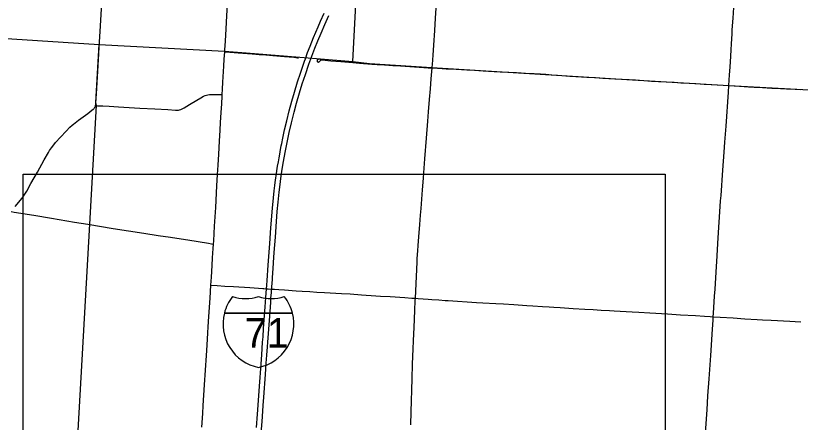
# Model space of a CAD drawing. Extents: x 1813937 to 1948437, y 826606 to 1022856.
# Drawn here: x 1873573 to 1890191, y 875827 to 884433 of the extents above; entities that cross this region are included whole.
import ezdxf

# ---------------------------------------------------------------- set-up
doc = ezdxf.new("R2010")
doc.units = 0
for name, color, linetype in [('Default', 7, 'Continuous'), ('GM_X_County_Road', 7, 'Continuous'), ('GM_X_Interstate_Route', 7, 'Continuous'), ('GM_X_Interstate_Shield', 7, 'Continuous'), ('GM_X_State_Route', 7, 'Continuous'), ('GM_X_Township', 7, 'Continuous'), ('GM_X_Township_Road', 7, 'Continuous')]:
    doc.layers.add(name, color=color, linetype=linetype)

msp = doc.modelspace()

# ---------------------------------------------------------------- linework, layer by layer
at = {"layer": 'Default'}
for p, q in [((1873729, 881082), (1887329, 881082)), ((1873729, 867482), (1873729, 881082)), ((1887329, 881082), (1887329, 867482))]:
    msp.add_line(p, q, dxfattribs=at)
at = {"layer": 'GM_X_County_Road'}
for points in [[(1875340, 883767), (1875347, 883875), (1875368, 884219), (1875408, 884824), (1875439, 885315), (1875466, 885691), (1875483, 885919), (1875493, 886066), (1875504, 886222), (1875516, 886361), (1875526, 886521)], [(1882394, 883327), (1882396, 883347), (1882399, 883397), (1882414, 883594), (1882429, 883806), (1882450, 884118), (1882466, 884380), (1882480, 884592), (1882489, 884773), (1882494, 884904), (1882502, 885051), (1882505, 885117), (1882513, 885297), (1882517, 885379), (1882523, 885510), (1882528, 885641), (1882535, 885805), (1882538, 885887), (1882542, 885985), (1882549, 886108)], [(1888677, 882955), (1888685, 883069), (1888692, 883183), (1888703, 883347), (1888718, 883576), (1888726, 883707), (1888734, 883838), (1888745, 884050), (1888750, 884132), (1888766, 884378), (1888781, 884607), (1888793, 884803), (1888810, 885032), (1888820, 885196), (1888836, 885408), (1888848, 885605), (1888852, 885654)], [(1875266, 882530), (1875266, 882534), (1875270, 882552), (1875273, 882582), (1875284, 882778), (1875304, 883138), (1875332, 883629), (1875340, 883767)], [(1882038, 878451), (1882059, 878916), (1882067, 879063), (1882075, 879227), (1882079, 879292), (1882092, 879456), (1882100, 879570), (1882113, 879750), (1882133, 880012), (1882147, 880208), (1882159, 880355), (1882177, 880550), (1882193, 880747), (1882211, 880992), (1882219, 881106), (1882242, 881401), (1882275, 881842), (1882302, 882202), (1882319, 882398), (1882339, 882659), (1882357, 882888), (1882375, 883100), (1882394, 883327)], [(1888348, 878062), (1888353, 878138), (1888376, 878498), (1888385, 878646), (1888407, 879006), (1888429, 879349), (1888446, 879611), (1888466, 879955), (1888479, 880167), (1888504, 880511), (1888512, 880625), (1888551, 881165), (1888578, 881541), (1888593, 881754), (1888619, 882097), (1888670, 882817), (1888677, 882955)], [(1873563, 880397), (1873708, 880574), (1873766, 880653), (1873810, 880722), (1873897, 880880), (1874034, 881123), (1874179, 881380), (1874268, 881537), (1874293, 881579), (1874329, 881637), (1874358, 881675), (1874420, 881751), (1874520, 881860), (1874642, 881992), (1874723, 882074), (1874772, 882118), (1874795, 882136), (1874902, 882219), (1875099, 882366), (1875189, 882435), (1875213, 882453), (1875226, 882465), (1875239, 882478), (1875244, 882483), (1875248, 882489), (1875253, 882497), (1875256, 882503), (1875261, 882512), (1875264, 882521), (1875266, 882530)], [(1881944, 875773), (1881952, 876049), (1881957, 876279), (1881964, 876508), (1881971, 876754), (1881981, 877049), (1881987, 877229), (1881993, 877376), (1881999, 877557), (1882012, 877835), (1882028, 878195), (1882036, 878408), (1882038, 878451)], [(1888128, 874784), (1888154, 875161), (1888190, 875701), (1888216, 876094), (1888235, 876388), (1888258, 876748), (1888294, 877238), (1888331, 877795), (1888344, 877991), (1888348, 878062)]]:
    msp.add_lwpolyline(points, dxfattribs=at)
at = {"layer": 'GM_X_Interstate_Route'}
for points in [[(1878674, 875720), (1878695, 875998), (1878743, 876686), (1878764, 876964), (1878785, 877258), (1878803, 877520), (1878812, 877635), (1878825, 877815), (1878858, 878273), (1878872, 878469), (1878886, 878654), (1878892, 878731), (1878899, 878829), (1878923, 879156), (1878956, 879615), (1878979, 879942), (1878997, 880187), (1879012, 880367), (1879024, 880498), (1879032, 880579), (1879048, 880726), (1879062, 880840), (1879071, 880905), (1879084, 881002), (1879096, 881083), (1879106, 881148), (1879121, 881246), (1879137, 881343), (1879151, 881423), (1879165, 881504), (1879183, 881601), (1879198, 881682), (1879207, 881730), (1879230, 881842), (1879268, 882019), (1879313, 882210), (1879365, 882417), (1879421, 882623), (1879476, 882812), (1879543, 883031), (1879604, 883218), (1879688, 883467), (1879708, 883521), (1879755, 883652), (1879808, 883790), (1879882, 883972), (1879977, 884199), (1880029, 884319), (1880104, 884483)], [(1879025, 879077), (1879033, 879208), (1879048, 879421), (1879074, 879748), (1879098, 880075), (1879114, 880288), (1879132, 880484), (1879154, 880696), (1879174, 880859), (1879192, 880989), (1879213, 881135), (1879242, 881314), (1879287, 881572), (1879328, 881782), (1879366, 881958), (1879414, 882166), (1879470, 882389), (1879522, 882579), (1879585, 882799), (1879643, 882988), (1879709, 883191), (1879784, 883408), (1879823, 883517), (1879845, 883578), (1879909, 883746), (1879971, 883899), (1880040, 884065), (1880118, 884246), (1880206, 884440)], [(1878974, 878366), (1878980, 878456), (1878989, 878571), (1878993, 878636), (1878994, 878648), (1878995, 878653), (1879000, 878718), (1879002, 878750), (1879020, 878996), (1879025, 879077)], [(1878830, 876359), (1878863, 876837), (1878881, 877082), (1878893, 877246), (1878907, 877426), (1878914, 877524), (1878946, 877982), (1878974, 878366)], [(1878793, 875843), (1878801, 875953), (1878818, 876182), (1878830, 876359)], [(1878598, 873152), (1878604, 873221), (1878610, 873303), (1878643, 873777), (1878677, 874252), (1878689, 874415), (1878696, 874510), (1878738, 875086), (1878768, 875511), (1878793, 875843)]]:
    msp.add_lwpolyline(points, dxfattribs=at)
at = {"layer": 'GM_X_Interstate_Shield'}
for p, q in [((1877993, 878137), (1879436, 878137)), ((1879436, 878137), (1877993, 878137)), ((1879436, 878137), (1877993, 878137))]:
    msp.add_line(p, q, dxfattribs=at)
for centre, start, end in [((1878902, 877907), 141.669, 165.8066), ((1878441, 879385), 253.0091, 286.9909), ((1878989, 879385), 253.0091, 286.9909), ((1878527, 877907), 14.1934, 38.331), ((1878902, 877907), 165.8066, 258.463), ((1878527, 877907), 281.537, 14.1934)]:
    msp.add_arc(centre, 938, start, end, dxfattribs=at)
at = {"layer": 'GM_X_State_Route'}
msp.add_lwpolyline([(1877518, 875722), (1877537, 876017), (1877547, 876181), (1877573, 876623), (1877594, 876933), (1877615, 877244), (1877628, 877457), (1877644, 877719), (1877652, 877850), (1877666, 878063), (1877691, 878456), (1877708, 878729), (1877719, 878897), (1877733, 879143), (1877743, 879307), (1877756, 879503), (1877763, 879600), (1877767, 879667), (1877786, 879978), (1877810, 880371), (1877837, 880829), (1877851, 881075), (1877861, 881271), (1877875, 881500), (1877892, 881779), (1877905, 882008), (1877914, 882172), (1877926, 882384), (1877936, 882565), (1877946, 882728), (1877948, 882762), (1877955, 882875), (1877963, 883023), (1877969, 883137), (1877983, 883366), (1877991, 883514), (1878002, 883665), (1878004, 883711), (1878014, 883891), (1878029, 884153), (1878044, 884431), (1878059, 884676)], dxfattribs=at)
at = {"layer": 'GM_X_Township'}
for points in [[(1880714, 883463), (1880836, 885744), (1880863, 886256), (1881338, 891636), (1881703, 897023), (1881803, 900282), (1881806, 900375), (1881918, 903829), (1881985, 905459), (1882074, 908232), (1882082, 908847), (1882260, 912507), (1887758, 913255), (1888309, 913332)], [(1850147, 879854), (1850364, 882693), (1850523, 884772), (1850567, 885340), (1853740, 885139), (1854805, 885081), (1854864, 885092), (1854977, 885091), (1857606, 884909), (1869894, 884174), (1875339, 883824)], [(1873671, 857558), (1873806, 859043), (1874029, 862389), (1874586, 870801), (1874844, 874776), (1875147, 880018), (1875287, 882532), (1875268, 882593), (1875339, 883824), (1877996, 883681), (1878453, 883649), (1879771, 883544), (1879947, 883530), (1880714, 883463), (1881064, 883424), (1881619, 883383), (1882389, 883337), (1886519, 883080), (1888679, 882953), (1894036, 882664)]]:
    msp.add_lwpolyline(points, dxfattribs=at)
at = {"layer": 'GM_X_Township_Road'}
for points in [[(1878002, 883665), (1878106, 883658), (1878204, 883653), (1878286, 883647), (1878580, 883626), (1878727, 883615), (1878874, 883604), (1879022, 883592), (1879267, 883571), (1879462, 883552), (1879544, 883542), (1879560, 883541)], [(1880034, 883504), (1880028, 883507), (1880019, 883510), (1880011, 883512), (1880003, 883513), (1879995, 883513), (1879987, 883512), (1879979, 883509), (1879975, 883507), (1879971, 883505), (1879965, 883500), (1879961, 883493), (1879958, 883486), (1879956, 883477), (1879957, 883474), (1879957, 883470), (1879959, 883466), (1879962, 883460), (1879965, 883458), (1879970, 883455), (1879975, 883453), (1879981, 883452), (1879987, 883452), (1879993, 883454), (1879999, 883457), (1880006, 883461), (1880018, 883471), (1880041, 883496), (1880045, 883498), (1880050, 883501), (1880055, 883502), (1880060, 883502), (1880071, 883502), (1880185, 883486), (1880251, 883480), (1880463, 883461), (1880627, 883448), (1880715, 883441)], [(1880715, 883441), (1880856, 883429), (1881118, 883410), (1881232, 883401), (1881297, 883397), (1881559, 883380), (1881723, 883370), (1881919, 883358), (1882116, 883345), (1882312, 883332), (1882394, 883327)], [(1882394, 883327), (1882410, 883326), (1882607, 883314), (1882689, 883309), (1882901, 883298), (1883131, 883286), (1883294, 883278), (1883475, 883268), (1883589, 883262), (1883704, 883254), (1883835, 883247), (1884019, 883237), (1884179, 883228), (1884277, 883221), (1884368, 883217), (1884462, 883211), (1884555, 883206), (1884686, 883199), (1884801, 883192), (1884931, 883183), (1885046, 883175), (1885144, 883168), (1885308, 883156), (1885439, 883148), (1885668, 883133), (1885853, 883122), (1886007, 883113), (1886266, 883098), (1886420, 883088), (1886567, 883081), (1886698, 883072), (1886878, 883059), (1887042, 883049), (1887190, 883043), (1887353, 883033), (1887517, 883024), (1887664, 883014), (1887845, 883004), (1887976, 882996), (1888156, 882985), (1888303, 882977), (1888434, 882969), (1888677, 882955)], [(1888677, 882955), (1888900, 882943), (1889097, 882929), (1889212, 882923), (1889392, 882913), (1889589, 882902), (1889638, 882899), (1889900, 882886), (1890081, 882876), (1890195, 882871)], [(1875266, 882530), (1875306, 882528), (1875421, 882525), (1875552, 882518), (1875748, 882505), (1876206, 882479), (1876517, 882462), (1876795, 882444), (1876959, 882433), (1876992, 882433), (1877008, 882434), (1877024, 882436), (1877040, 882439), (1877072, 882448), (1877102, 882461), (1877145, 882484), (1877257, 882552), (1877411, 882647), (1877496, 882696), (1877553, 882728), (1877583, 882741), (1877614, 882752), (1877646, 882760), (1877678, 882764), (1877727, 882765), (1877875, 882762), (1877924, 882762), (1877948, 882762)], [(1873476, 880289), (1873540, 880278), (1873961, 880210), (1874333, 880147), (1874819, 880066), (1875101, 880019)], [(1875101, 880019), (1875637, 879932), (1876284, 879831), (1876591, 879783), (1876850, 879743), (1877076, 879709), (1877222, 879686), (1877659, 879618), (1877723, 879607), (1877763, 879600)], [(1877708, 878729), (1877716, 878729), (1877839, 878720), (1878005, 878708), (1878185, 878698), (1878529, 878677), (1878807, 878659), (1878830, 878658)], [(1878830, 878658), (1878886, 878654), (1878922, 878652), (1878994, 878648), (1879053, 878644), (1879146, 878637)], [(1879146, 878637), (1879265, 878628), (1879511, 878612), (1879642, 878604), (1879805, 878594), (1879953, 878584), (1880116, 878574), (1880477, 878554), (1880657, 878543), (1880898, 878527), (1881200, 878506), (1881299, 878499), (1881507, 878487), (1881818, 878467), (1881965, 878456), (1882014, 878452), (1882030, 878451), (1882038, 878451)], [(1882038, 878451), (1882096, 878449), (1882309, 878433), (1882390, 878428), (1882537, 878417), (1882668, 878408), (1882700, 878405), (1882733, 878403)], [(1882733, 878403), (1883334, 878366), (1883465, 878359), (1883744, 878343), (1883908, 878335), (1884124, 878321), (1884399, 878302), (1884527, 878294), (1884729, 878281), (1884874, 878270), (1884972, 878264), (1885103, 878255), (1885381, 878239), (1885627, 878225), (1885807, 878215), (1885971, 878204), (1886151, 878194), (1886249, 878189), (1886627, 878166), (1886773, 878156), (1887002, 878142), (1887379, 878120), (1887657, 878103), (1887969, 878086), (1888165, 878074), (1888280, 878067), (1888348, 878062)], [(1888348, 878062), (1888493, 878053), (1888771, 878035), (1889017, 878020), (1889279, 878004), (1889393, 877997), (1889574, 877988), (1889972, 877965), (1890083, 877958), (1890202, 877951)]]:
    msp.add_lwpolyline(points, dxfattribs=at)

# ---------------------------------------------------------------- texts
at = {"layer": 'GM_X_Interstate_Shield'}
msp.add_text('71', height=625, dxfattribs=at).set_placement((1878426, 877410))

doc.saveas('drawing.dxf')
